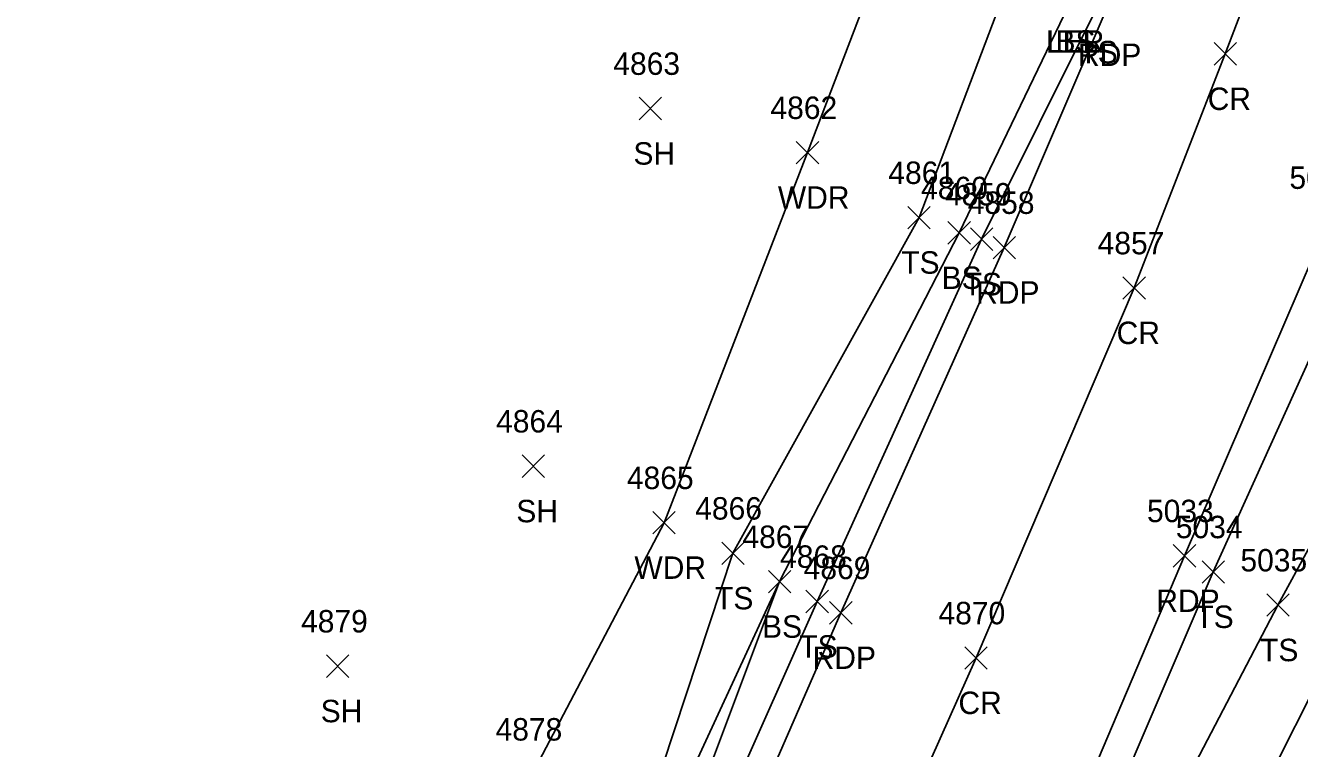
# Model space of a CAD drawing. Extents: x 1678863 to 1683592, y 407783 to 418211.
# Drawn here: x 1680049 to 1680162.6, y 412196.8 to 412261.2 of the extents above; entities that cross this region are included whole.
import ezdxf

# ---------------------------------------------------------------- set-up
doc = ezdxf.new("R2010")
doc.units = 0
for name, color, linetype in [('L_A', 7, 'Continuous'), ('L_I', 7, 'Continuous'), ('L_TIC', 7, 'Continuous'), ('LAWA', 7, 'Continuous'), ('LELB', 7, 'Continuous'), ('P_A', 7, 'Continuous'), ('P_I', 7, 'Continuous'), ('P_TIC', 7, 'Continuous'), ('PET', 7, 'Continuous'), ('PRC', 7, 'Continuous')]:
    doc.layers.add(name, color=color, linetype=linetype)

msp = doc.modelspace()

# ---------------------------------------------------------------- linework, layer by layer
at = {"layer": 'L_TIC'}
for points in [[(1680103.68, 412252.78), (1680105.68, 412254.78)], [(1680105.68, 412252.78), (1680103.68, 412254.78)], [(1680117.69, 412248.85), (1680119.69, 412250.85)], [(1680119.69, 412248.85), (1680117.69, 412250.85)], [(1680127.64, 412243.06), (1680129.64, 412245.06)], [(1680129.64, 412243.06), (1680127.64, 412245.06)], [(1680131.21, 412241.7), (1680133.21, 412243.7)], [(1680133.21, 412241.7), (1680131.21, 412243.7)], [(1680133.21, 412241.14), (1680135.21, 412243.14)], [(1680135.21, 412241.14), (1680133.21, 412243.14)], [(1680093.24, 412220.91), (1680095.24, 412222.91)], [(1680095.24, 412220.91), (1680093.24, 412222.91)], [(1680104.9, 412215.87), (1680106.9, 412217.87)], [(1680106.9, 412215.87), (1680104.9, 412217.87)], [(1680111.04, 412213.15), (1680113.04, 412215.15)], [(1680113.04, 412213.15), (1680111.04, 412215.15)], [(1680153.87, 412211.49), (1680155.87, 412213.49)], [(1680155.87, 412211.49), (1680153.87, 412213.49)], [(1680115.2, 412210.62), (1680117.2, 412212.62)], [(1680117.2, 412210.62), (1680115.2, 412212.62)], [(1680115.2, 412210.62), (1680117.2, 412212.62)], [(1680117.2, 412210.62), (1680115.2, 412212.62)], [(1680118.55, 412208.85), (1680120.55, 412210.85)], [(1680120.55, 412208.85), (1680118.55, 412210.85)], [(1680159.63, 412208.53), (1680161.63, 412210.53)], [(1680161.63, 412208.53), (1680159.63, 412210.53)], [(1680075.8, 412203.09), (1680077.8, 412205.09)], [(1680077.8, 412203.09), (1680075.8, 412205.09)]]:
    msp.add_lwpolyline(points, dxfattribs=at)
at = {"layer": 'LAWA'}
msp.add_lwpolyline([(1680135.2, 412293), (1680118.69, 412249.85), (1680105.9, 412216.87), (1680094.14, 412194.46), (1680067.77, 412162.81), (1680057.96, 412126.42), (1680041.15, 412080.95), (1680031.02, 412053.6), (1680016.17, 412044.38), (1680000.69, 412011.21), (1679988.54, 411967.04), (1679972.85, 411936.59), (1679960.21, 411896.58), (1679935.08, 411878.15)], dxfattribs=at)
at = {"layer": 'LELB'}
for points in [[(1680193.49, 412307.14), (1680185.67, 412276.04), (1680182.93, 412254.01), (1680178.28, 412245.87), (1680174.45, 412233.83), (1680169.26, 412225.38), (1680160.63, 412209.53), (1680144.21, 412178.12), (1680137.73, 412164.62), (1680149.85, 412156.23), (1680159.82, 412146.58), (1680145.76, 412151.3), (1680133.57, 412155.76)], [(1680145.73, 412289.13), (1680128.64, 412244.06), (1680112.04, 412214.15), (1680103.67, 412188.89), (1680088.28, 412165.03), (1680089.1, 412153.87), (1680074.8, 412121.02), (1680052.39, 412075.6), (1680033.43, 412033.73), (1680018.93, 412003.28), (1680008.8, 411990.41), (1680001.02, 411961.46), (1679989.06, 411929.83), (1679973.05, 411890.32), (1679959.41, 411862.54), (1679945.49, 411821.76), (1679931.28, 411789.27), (1679912.41, 411754.31), (1679901.71, 411732.57), (1679883.38, 411700.41), (1679870.87, 411667.28), (1679856.09, 411644.32), (1679840.75, 411634.34), (1679825.19, 411634.62)], [(1680180.36, 412277.86), (1680168.7, 412243.07), (1680154.87, 412212.49), (1680140.8, 412179.71), (1680119.65, 412133.11), (1680104.24, 412097.21), (1680097.81, 412085.37), (1680082.37, 412049.15), (1680070.07, 412019.34), (1680054.78, 411987.66), (1680043.57, 411963.06), (1680034.28, 411944.45)], [(1680142.36, 412263.76), (1680132.21, 412242.7), (1680116.2, 412211.62), (1680107.1, 412187.4), (1680098.39, 412169.04), (1680096.55, 412165.38), (1680095.14, 412162.01), (1680092.3, 412152.44), (1680078.27, 412119.77), (1680056.88, 412071.05), (1680038.9, 412031.76), (1680024.62, 411998.8), (1680007.47, 411959.51), (1679994.05, 411928.03), (1679977.53, 411889.44), (1679963.99, 411860.67), (1679946.53, 411820.94), (1679932.49, 411788.7), (1679915.8, 411752.44), (1679905.29, 411730.27), (1679888.9, 411697.07), (1679874.39, 411665.69), (1679857.86, 411640.18)], [(1680144.52, 412262.81), (1680134.21, 412242.14), (1680119.55, 412209.85), (1680109.08, 412186.36), (1680093.78, 412151.15), (1680079.71, 412119.43), (1680058.33, 412069.92), (1680041.01, 412030.93), (1680026.25, 411998.23), (1680008.22, 411958.95), (1679995.34, 411926.87), (1679978.52, 411888.99), (1679966.38, 411859.27), (1679948.84, 411819.72), (1679934.84, 411787.59), (1679917.47, 411751.9), (1679908.09, 411729.17), (1679891.61, 411695.95), (1679874.39, 411665.69)], [(1680203.47, 412225.34), (1680176.15, 412223.96), (1680166.07, 412206.49), (1680150.56, 412175.6), (1680142.85, 412169.03), (1680152.46, 412160.22), (1680159.82, 412146.58), (1680156.26, 412141.69), (1680145.59, 412146.04), (1680131.32, 412151.03), (1680130.66, 412149.63), (1680155.37, 412139.68)], [(1680116.2, 412211.62), (1680105.27, 412187.98), (1680096.6, 412169.91), (1680095.14, 412165.62), (1680094.07, 412162.48), (1680091.23, 412152.57), (1680076.63, 412120.69), (1680055, 412072.2), (1680037.76, 412032.09), (1680021.83, 412000.29), (1680004.5, 411960.74), (1679991.98, 411928.77), (1679976.84, 411889.51), (1679963.99, 411860.67)]]:
    msp.add_lwpolyline(points, dxfattribs=at)
at = {"layer": 'P_TIC'}
for points in [[(1680154.94, 412257.65), (1680156.94, 412259.65)], [(1680156.94, 412257.65), (1680154.94, 412259.65)], [(1680135.24, 412240.39), (1680137.24, 412242.39)], [(1680137.24, 412240.39), (1680135.24, 412242.39)], [(1680146.82, 412236.79), (1680148.82, 412238.79)], [(1680148.82, 412236.79), (1680146.82, 412238.79)], [(1680151.3, 412212.92), (1680153.3, 412214.92)], [(1680153.3, 412212.92), (1680151.3, 412214.92)], [(1680120.66, 412207.84), (1680122.66, 412209.84)], [(1680122.66, 412207.84), (1680120.66, 412209.84)], [(1680132.72, 412203.82), (1680134.72, 412205.82)], [(1680134.72, 412203.82), (1680132.72, 412205.82)]]:
    msp.add_lwpolyline(points, dxfattribs=at)
at = {"layer": 'PET'}
for points in [[(1680178.4, 412278.7), (1680165.09, 412243.62), (1680152.3, 412213.92), (1680138.21, 412180.74), (1680126.17, 412152.91), (1680125.6, 412151.88), (1680117.96, 412134.41), (1680101.99, 412098.14), (1680096.46, 412085.51), (1680080.77, 412050.26), (1680067.09, 412020.1), (1680053.27, 411987.99), (1680042.26, 411963.31), (1680034.28, 411944.45), (1680029.37, 411933.14), (1680011.19, 411890.71)], [(1680145.32, 412262.57), (1680136.24, 412241.39), (1680121.66, 412208.84), (1680111.54, 412185.6), (1680095.73, 412150.37), (1680081.67, 412118.96), (1680059.32, 412069.56), (1680041.8, 412030.33), (1680027.57, 411997.55), (1680010.3, 411957.8), (1679996.66, 411926.17), (1679980.17, 411888.2), (1679967.46, 411858.86), (1679950.06, 411818.92), (1679935.77, 411786.58), (1679919.74, 411750.92), (1679909.04, 411728.72), (1679893.03, 411695.21), (1679877.78, 411664.11), (1679867.25, 411644.06), (1679850.71, 411612.74)]]:
    msp.add_lwpolyline(points, dxfattribs=at)
at = {"layer": 'PRC'}
msp.add_lwpolyline([(1680165.53, 412283.79), (1680155.94, 412258.65), (1680147.82, 412237.79), (1680133.72, 412204.82), (1680123.36, 412181.6), (1680106.63, 412144.64), (1680093.46, 412114.23), (1680070.71, 412063.4), (1680053.42, 412025.03), (1680039.21, 411992.49), (1680022.22, 411953.1), (1680008.12, 411920.68), (1679992.23, 411883.53), (1679979.18, 411853.54), (1679961.98, 411814.49), (1679947.28, 411781.69), (1679931.49, 411746.86), (1679920.33, 411722.96), (1679902.4, 411685.24), (1679884.42, 411649.11), (1679864.9, 411612.28)], dxfattribs=at)

# ---------------------------------------------------------------- texts
at = {"layer": 'L_A'}
for s, p in [('LER', (1680139.95, 412258.76)), ('LEL', (1680140, 412258.76)), ('BS', (1680140.8, 412258.76)), ('TS', (1680142.93, 412257.81)), ('SH', (1680103.17, 412248.78)), ('WDR', (1680116.05, 412244.85)), ('TS', (1680127.05, 412239.06)), ('BS', (1680130.65, 412237.7)), ('TS', (1680132.61, 412237.14)), ('SH', (1680092.73, 412216.91)), ('WDR', (1680103.26, 412211.87)), ('TS', (1680110.45, 412209.15)), ('BS', (1680114.64, 412206.62)), ('BS', (1680114.64, 412206.62)), ('TS', (1680153.27, 412207.49)), ('TS', (1680117.96, 412204.85)), ('TS', (1680159.04, 412204.53)), ('SH', (1680075.29, 412199.09))]:
    msp.add_text(s, height=2, dxfattribs=at).set_placement(p)
at = {"layer": 'L_I'}
for s, p in [('4863', (1680101.38, 412256.78)), ('4862', (1680115.39, 412252.85)), ('4861', (1680125.9, 412247.06)), ('4860', (1680128.82, 412245.7)), ('4859', (1680130.94, 412245.14)), ('4864', (1680090.93, 412224.91)), ('4865', (1680102.59, 412219.87)), ('4866', (1680108.68, 412217.15)), ('4867', (1680112.89, 412214.62)), ('4867', (1680112.89, 412214.62)), ('5034', (1680151.53, 412215.49)), ('4868', (1680116.25, 412212.85)), ('5035', (1680157.29, 412212.53)), ('4879', (1680073.54, 412207.09)), ('4878', (1680090.88, 412197.46))]:
    msp.add_text(s, height=2, dxfattribs=at).set_placement(p)
at = {"layer": 'P_A'}
for s, p in [('RDP', (1680142.81, 412257.57)), ('CR', (1680154.37, 412253.65)), ('RDP', (1680133.73, 412236.39)), ('CR', (1680146.25, 412232.79)), ('RDP', (1680149.79, 412208.92)), ('RDP', (1680119.15, 412203.84)), ('CR', (1680132.15, 412199.82))]:
    msp.add_text(s, height=2, dxfattribs=at).set_placement(p)
at = {"layer": 'P_I'}
for s, p in [('5020', (1680161.66, 412246.62)), ('4858', (1680132.98, 412244.39)), ('4857', (1680144.56, 412240.79)), ('5033', (1680148.96, 412216.92)), ('4869', (1680118.35, 412211.84)), ('4870', (1680130.37, 412207.82))]:
    msp.add_text(s, height=2, dxfattribs=at).set_placement(p)

doc.saveas('drawing.dxf')
